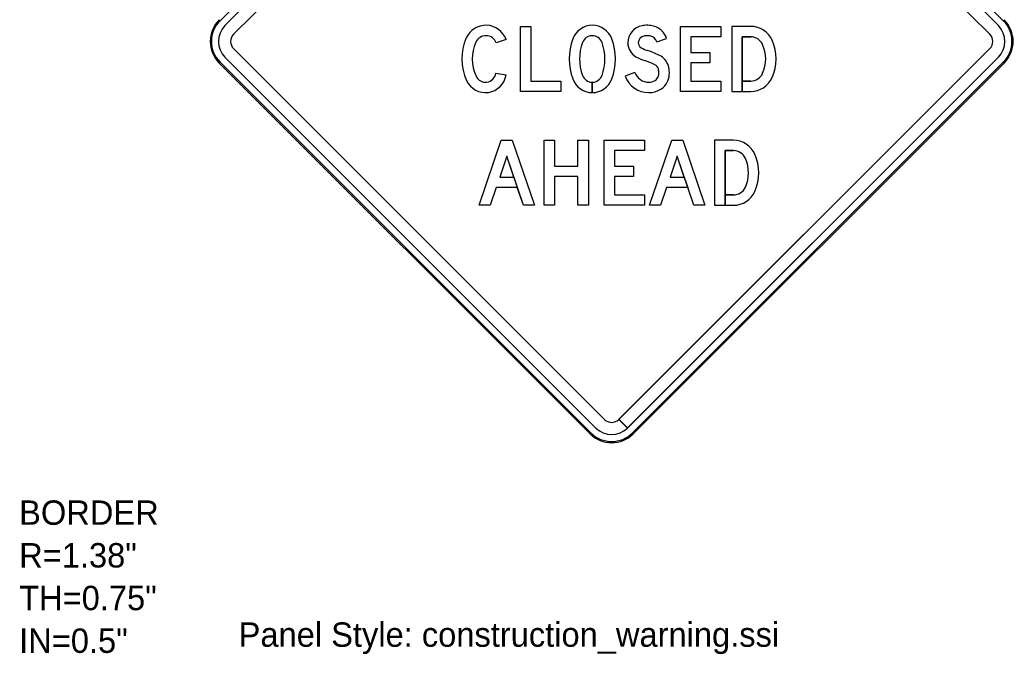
# Model space of a CAD drawing. Extents: x 1788.1 to 1851.2, y 237.2 to 283.4.
# Drawn here: x 1804.67 to 1810.78, y 273.18 to 277.08 of the extents above; entities that cross this region are included whole.
import ezdxf

# ---------------------------------------------------------------- set-up
doc = ezdxf.new("R2010")
doc.units = 0
for name, color, linetype in [('GSBWFILL', 7, 'Continuous'), ('GSCOLORFILL', 7, 'Continuous'), ('GSDIMS', 7, 'Continuous'), ('GSOUTLINE', 7, 'Continuous')]:
    doc.layers.add(name, color=color, linetype=linetype)

msp = doc.modelspace()

# ---------------------------------------------------------------- linework, layer by layer
at = {"layer": 'GSBWFILL'}
for p, q in [((1808.2153, 279.3253), (1805.9352, 277.0452)), ((1810.6898, 277.0452), (1808.4097, 279.3253)), ((1805.9882, 276.9922), (1808.2683, 279.2722)), ((1808.3567, 279.2722), (1810.6368, 276.9922)), ((1808.2683, 274.6237), (1805.9882, 276.9038)), ((1807.6632, 276.9606), (1807.6031, 276.9387)), ((1810.6368, 276.9038), (1808.3572, 274.6242)), ((1805.9352, 276.8507), (1808.2153, 274.5707)), ((1808.4103, 274.5712), (1810.6898, 276.8507)), ((1805.8997, 276.8152), (1808.1797, 274.5351)), ((1808.4453, 274.5351), (1810.7253, 276.8152)), ((1807.5999, 276.7519), (1807.6632, 276.7425)), ((1808.1932, 276.6974), (1808.1932, 276.6334)), ((1808.1933, 276.6334), (1808.1933, 276.6974)), ((1809.1674, 276.7044), (1809.1153, 276.7044)), ((1809.0614, 276.0044), (1809.0093, 276.0044)), ((1808.4097, 274.5707), (1808.3567, 274.6237)), ((1808.3572, 274.6242), (1808.4103, 274.5712))]:
    msp.add_line(p, q, dxfattribs=at)
for points in [[(1807.8152, 276.7044), (1807.9992, 276.7044), (1807.9992, 276.6404), (1807.7512, 276.6404), (1807.7512, 277.0404), (1807.8152, 277.0404)], [(1808.9832, 276.9764), (1808.7992, 276.9764), (1808.7992, 276.8804), (1808.9156, 276.8804), (1808.9156, 276.8164), (1808.7992, 276.8164), (1808.7992, 276.7044), (1808.9832, 276.7044), (1808.9832, 276.6404), (1808.7352, 276.6404), (1808.7352, 277.0404), (1808.9832, 277.0404)], [(1807.4973, 275.9404), (1807.6333, 276.3404), (1807.7013, 276.3404), (1807.8373, 275.9404), (1807.7697, 275.9404), (1807.6673, 276.2416), (1807.624, 276.1143), (1807.7105, 276.1143), (1807.7323, 276.0503), (1807.6023, 276.0503), (1807.5649, 275.9404)], [(1807.8973, 276.3404), (1807.9613, 276.3404), (1807.9613, 276.1804), (1808.1053, 276.1804), (1808.1053, 276.3404), (1808.1693, 276.3404), (1808.1693, 275.9404), (1808.1053, 275.9404), (1808.1053, 276.1164), (1807.9613, 276.1164), (1807.9613, 275.9404), (1807.8973, 275.9404)], [(1808.5133, 276.2764), (1808.3293, 276.2764), (1808.3293, 276.1804), (1808.4456, 276.1804), (1808.4456, 276.1164), (1808.3293, 276.1164), (1808.3293, 276.0044), (1808.5133, 276.0044), (1808.5133, 275.9404), (1808.2653, 275.9404), (1808.2653, 276.3404), (1808.5133, 276.3404)], [(1808.5453, 275.9404), (1808.6813, 276.3404), (1808.7493, 276.3404), (1808.8853, 275.9404), (1808.8177, 275.9404), (1808.7153, 276.2416), (1808.672, 276.1143), (1808.7585, 276.1143), (1808.7803, 276.0503), (1808.6503, 276.0503), (1808.6129, 275.9404)]]:
    msp.add_lwpolyline(points, close=True, dxfattribs=at)
for points in [[(1809.1674, 277.0404), (1809.0512, 277.0404), (1809.0512, 276.6404), (1809.1152, 276.6404), (1809.1152, 276.9764), (1809.1674, 276.9764)], [(1808.5892, 276.9461), (1808.6499, 276.9664)], [(1808.4551, 276.7567), (1808.3952, 276.7341)], [(1809.1153, 276.7044), (1809.1153, 276.6404), (1809.1674, 276.6404)], [(1809.0614, 276.3404), (1808.9453, 276.3404), (1808.9453, 275.9404), (1809.0093, 275.9404), (1809.0093, 276.2764), (1809.0614, 276.2764)], [(1809.0093, 276.0044), (1809.0093, 275.9404), (1809.0614, 275.9404)]]:
    msp.add_lwpolyline(points, dxfattribs=at)
for centre, radius, start, end in [((1806.0324, 276.948), 0.1878, 135, 225), ((1806.0324, 276.948), 0.1375, 135, 225), ((1809.1674, 276.8964), 0.144, 23.94109, 90), ((1810.5926, 276.948), 0.1375, 315, 45), ((1810.5926, 276.948), 0.1878, 315, 45), ((1806.0324, 276.948), 0.0625, 135, 225), ((1809.1674, 276.8964), 0.08, 23.94109, 90), ((1810.5926, 276.948), 0.0625, 315, 45), ((1809.0412, 276.8404), 0.218, 336.05891, 23.94109), ((1809.0412, 276.8404), 0.282, 336.05891, 23.94109), ((1809.1674, 276.7844), 0.08, 270, 336.05891), ((1809.1674, 276.7844), 0.144, 270, 336.05891), ((1809.0614, 276.1964), 0.144, 23.94109, 90), ((1809.0614, 276.1964), 0.08, 23.94109, 90), ((1808.9353, 276.1404), 0.282, 336.05891, 23.94109), ((1808.9353, 276.1404), 0.218, 336.05891, 23.94109), ((1809.0614, 276.0844), 0.08, 270, 336.05891), ((1809.0614, 276.0844), 0.144, 270, 336.05891), ((1808.3125, 274.6679), 0.0625, 225, 315), ((1808.3125, 274.6679), 0.1878, 225, 315), ((1808.3125, 274.6679), 0.1375, 225, 315)]:
    msp.add_arc(centre, radius, start, end, dxfattribs=at)
for centre, major_axis, start_param, end_param in [((1807.5392, 276.9154), (0, 0.132), 5.061866, 7.434148), ((1808.1932, 276.9194), (0, 0.128), 5.063177, 7.503193), ((1808.5184, 276.9395), (0, 0.1066), 0.175685, 1.570796), ((1808.5301, 276.8736), (0, 0.1735), 0.090794, 0.175685), ((1808.5355, 276.8147), (0, 0.2326), 6.283185, 6.373979), ((1808.5355, 276.92), (0, 0.1273), 6.012094, 6.283185), ((1808.538, 276.9291), (0, 0.118), 5.034126, 6.012094), ((1807.7072, 276.8404), (0, 0.316), 1.150963, 2.004476), ((1807.5392, 276.9154), (0, 0.068), 5.061866, 7.434148), ((1808.4091, 276.8404), (0, 0.3579), 1.220008, 1.921585), ((1808.1932, 276.9194), (0, 0.064), 5.063177, 7.503193), ((1807.9773, 276.8404), (0, 0.3579), 4.361601, 5.063177), ((1808.5184, 276.9395), (0, 0.0426), 0.175685, 1.570796), ((1808.5301, 276.8736), (0, 0.1095), 0.090794, 0.175685), ((1808.5355, 276.8147), (0, 0.1686), 0, 0.090794), ((1808.5355, 276.92), (0, 0.0633), 6.012094, 6.283185), ((1808.538, 276.9291), (0, 0.054), 5.034126, 6.012094), ((1807.7072, 276.8404), (0, 0.252), 1.150963, 2.004476), ((1808.4091, 276.8404), (0, 0.2939), 1.220008, 1.921585), ((1807.9773, 276.8404), (0, 0.2939), 4.361601, 5.063177), ((1808.5104, 276.9395), (0, 0.0986), 1.570796, 2.627164), ((1808.5104, 276.9395), (0, 0.0346), 1.570796, 2.627164), ((1808.6008, 277.0994), (0, 0.2182), 2.627164, 2.834816), ((1808.6008, 277.0994), (0, 0.2822), 2.627164, 2.834816), ((1808.3849, 276.418), (0, 0.4965), 5.820582, 5.976409), ((1808.559, 276.7669), (0, 0.1066), 5.010707, 5.820582), ((1808.3849, 276.418), (0, 0.4325), 5.820582, 5.976409), ((1808.559, 276.7669), (0, 0.0426), 5.010707, 5.820582), ((1808.5225, 276.7557), (0, 0.0807), 4.712389, 5.010707), ((1808.5225, 276.7557), (0, 0.1447), 4.712389, 5.010707), ((1807.5366, 276.7614), (0, 0.128), 2.004476, 4.564141), ((1807.5366, 276.7614), (0, 0.064), 2.004476, 4.564141), ((1808.1932, 276.7614), (0, 0.064), 1.921585, 3.141593), ((1808.1932, 276.7614), (0, 0.064), 3.141905, 4.361601), ((1808.5409, 276.789), (0, 0.1556), 1.931277, 3.141593), ((1808.5409, 276.789), (0, 0.0916), 1.931277, 3.141593), ((1808.5554, 276.7476), (0, 0.0462), 3.672524, 4.331279), ((1808.5351, 276.7557), (0, 0.0682), 4.331279, 4.712389), ((1808.5351, 276.7557), (0, 0.1322), 4.331279, 4.712389), ((1808.1932, 276.7614), (0, 0.128), 1.921585, 3.141593), ((1808.1932, 276.7614), (0, 0.128), 3.141749, 4.361601), ((1808.5409, 276.7724), (0, 0.075), 3.141593, 3.672524), ((1808.5554, 276.7476), (0, 0.1102), 3.672524, 4.331279), ((1808.5409, 276.7724), (0, 0.139), 3.141593, 3.672524)]:
    msp.add_ellipse(centre, major_axis=major_axis, ratio=0.999993, start_param=start_param, end_param=end_param, dxfattribs=at)
at = {"layer": 'GSCOLORFILL'}
for p, q in [((1805.905, 277.0754), (1808.185, 279.3555)), ((1808.44, 279.3555), (1810.72, 277.0754)), ((1808.2153, 279.3253), (1805.9352, 277.0452)), ((1810.6898, 277.0452), (1808.4097, 279.3253)), ((1805.9882, 276.9922), (1808.2683, 279.2722)), ((1808.3567, 279.2722), (1810.6368, 276.9922)), ((1808.2683, 274.6237), (1805.9882, 276.9038)), ((1807.6632, 276.9606), (1807.6031, 276.9387)), ((1810.6368, 276.9038), (1808.3572, 274.6242)), ((1805.9352, 276.8507), (1808.2153, 274.5707)), ((1808.4103, 274.5712), (1810.6898, 276.8507)), ((1805.8997, 276.8152), (1808.1797, 274.5351)), ((1805.8997, 276.8152), (1808.1797, 274.5351)), ((1808.185, 274.5404), (1805.905, 276.8205)), ((1810.72, 276.8205), (1808.44, 274.5405)), ((1808.4453, 274.5351), (1810.7253, 276.8152)), ((1808.4453, 274.5352), (1810.7253, 276.8152)), ((1807.5999, 276.7519), (1807.6632, 276.7425)), ((1808.1932, 276.6974), (1808.1932, 276.6334)), ((1808.1933, 276.6334), (1808.1933, 276.6974)), ((1809.1674, 276.7044), (1809.1153, 276.7044)), ((1809.0614, 276.0044), (1809.0093, 276.0044)), ((1808.4097, 274.5707), (1808.3567, 274.6237)), ((1808.3572, 274.6242), (1808.4103, 274.5712)), ((1808.44, 274.5405), (1808.4453, 274.5352)), ((1808.4453, 274.5351), (1808.44, 274.5404))]:
    msp.add_line(p, q, dxfattribs=at)
for points in [[(1807.8152, 276.7044), (1807.9992, 276.7044), (1807.9992, 276.6404), (1807.7512, 276.6404), (1807.7512, 277.0404), (1807.8152, 277.0404)], [(1808.9832, 276.9764), (1808.7992, 276.9764), (1808.7992, 276.8804), (1808.9156, 276.8804), (1808.9156, 276.8164), (1808.7992, 276.8164), (1808.7992, 276.7044), (1808.9832, 276.7044), (1808.9832, 276.6404), (1808.7352, 276.6404), (1808.7352, 277.0404), (1808.9832, 277.0404)], [(1807.4973, 275.9404), (1807.6333, 276.3404), (1807.7013, 276.3404), (1807.8373, 275.9404), (1807.7697, 275.9404), (1807.6673, 276.2416), (1807.624, 276.1143), (1807.7105, 276.1143), (1807.7323, 276.0503), (1807.6023, 276.0503), (1807.5649, 275.9404)], [(1807.8973, 276.3404), (1807.9613, 276.3404), (1807.9613, 276.1804), (1808.1053, 276.1804), (1808.1053, 276.3404), (1808.1693, 276.3404), (1808.1693, 275.9404), (1808.1053, 275.9404), (1808.1053, 276.1164), (1807.9613, 276.1164), (1807.9613, 275.9404), (1807.8973, 275.9404)], [(1808.5133, 276.2764), (1808.3293, 276.2764), (1808.3293, 276.1804), (1808.4456, 276.1804), (1808.4456, 276.1164), (1808.3293, 276.1164), (1808.3293, 276.0044), (1808.5133, 276.0044), (1808.5133, 275.9404), (1808.2653, 275.9404), (1808.2653, 276.3404), (1808.5133, 276.3404)], [(1808.5453, 275.9404), (1808.6813, 276.3404), (1808.7493, 276.3404), (1808.8853, 275.9404), (1808.8177, 275.9404), (1808.7153, 276.2416), (1808.672, 276.1143), (1808.7585, 276.1143), (1808.7803, 276.0503), (1808.6503, 276.0503), (1808.6129, 275.9404)]]:
    msp.add_lwpolyline(points, close=True, dxfattribs=at)
for points in [[(1809.1674, 277.0404), (1809.0512, 277.0404), (1809.0512, 276.6404), (1809.1152, 276.6404), (1809.1152, 276.9764), (1809.1674, 276.9764)], [(1808.5892, 276.9461), (1808.6499, 276.9664)], [(1808.4551, 276.7567), (1808.3952, 276.7341)], [(1809.1153, 276.7044), (1809.1153, 276.6404), (1809.1674, 276.6404)], [(1809.0614, 276.3404), (1808.9453, 276.3404), (1808.9453, 275.9404), (1809.0093, 275.9404), (1809.0093, 276.2764), (1809.0614, 276.2764)], [(1809.0093, 276.0044), (1809.0093, 275.9404), (1809.0614, 275.9404)]]:
    msp.add_lwpolyline(points, dxfattribs=at)
for centre, radius, start, end in [((1806.0324, 276.948), 0.1878, 135, 225), ((1806.0324, 276.948), 0.1878, 135, 225), ((1806.0324, 276.948), 0.1802, 135, 225), ((1806.0324, 276.948), 0.1375, 135, 225), ((1809.1674, 276.8964), 0.144, 23.94109, 90), ((1810.5926, 276.948), 0.1375, 315, 45), ((1810.5926, 276.948), 0.1802, 315, 45), ((1810.5926, 276.948), 0.1878, 315, 45), ((1810.5926, 276.948), 0.1878, 315, 45), ((1806.0324, 276.948), 0.0625, 135, 225), ((1809.1674, 276.8964), 0.08, 23.94109, 90), ((1810.5926, 276.948), 0.0625, 315, 45), ((1809.0412, 276.8404), 0.218, 336.05891, 23.94109), ((1809.0412, 276.8404), 0.282, 336.05891, 23.94109), ((1809.1674, 276.7844), 0.08, 270, 336.05891), ((1809.1674, 276.7844), 0.144, 270, 336.05891), ((1809.0614, 276.1964), 0.144, 23.94109, 90), ((1809.0614, 276.1964), 0.08, 23.94109, 90), ((1808.9353, 276.1404), 0.282, 336.05891, 23.94109), ((1808.9353, 276.1404), 0.218, 336.05891, 23.94109), ((1809.0614, 276.0844), 0.08, 270, 336.05891), ((1809.0614, 276.0844), 0.144, 270, 336.05891), ((1808.3125, 274.6679), 0.0625, 225, 315), ((1808.3125, 274.6679), 0.1878, 225, 315), ((1808.3125, 274.6679), 0.1878, 225, 315), ((1808.3125, 274.6679), 0.1802, 225, 315), ((1808.3125, 274.6679), 0.1375, 225, 315)]:
    msp.add_arc(centre, radius, start, end, dxfattribs=at)
for centre, major_axis, start_param, end_param in [((1807.5392, 276.9154), (0, 0.132), 5.061866, 7.434148), ((1808.1932, 276.9194), (0, 0.128), 5.063177, 7.503193), ((1808.5184, 276.9395), (0, 0.1066), 0.175685, 1.570796), ((1808.5301, 276.8736), (0, 0.1735), 0.090794, 0.175685), ((1808.5355, 276.8147), (0, 0.2326), 6.283185, 6.373979), ((1808.5355, 276.92), (0, 0.1273), 6.012094, 6.283185), ((1808.538, 276.9291), (0, 0.118), 5.034126, 6.012094), ((1807.7072, 276.8404), (0, 0.316), 1.150963, 2.004476), ((1807.5392, 276.9154), (0, 0.068), 5.061866, 7.434148), ((1808.4091, 276.8404), (0, 0.3579), 1.220008, 1.921585), ((1808.1932, 276.9194), (0, 0.064), 5.063177, 7.503193), ((1807.9773, 276.8404), (0, 0.3579), 4.361601, 5.063177), ((1808.5184, 276.9395), (0, 0.0426), 0.175685, 1.570796), ((1808.5301, 276.8736), (0, 0.1095), 0.090794, 0.175685), ((1808.5355, 276.8147), (0, 0.1686), 0, 0.090794), ((1808.5355, 276.92), (0, 0.0633), 6.012094, 6.283185), ((1808.538, 276.9291), (0, 0.054), 5.034126, 6.012094), ((1807.7072, 276.8404), (0, 0.252), 1.150963, 2.004476), ((1808.4091, 276.8404), (0, 0.2939), 1.220008, 1.921585), ((1807.9773, 276.8404), (0, 0.2939), 4.361601, 5.063177), ((1808.5104, 276.9395), (0, 0.0986), 1.570796, 2.627164), ((1808.5104, 276.9395), (0, 0.0346), 1.570796, 2.627164), ((1808.6008, 277.0994), (0, 0.2182), 2.627164, 2.834816), ((1808.6008, 277.0994), (0, 0.2822), 2.627164, 2.834816), ((1808.3849, 276.418), (0, 0.4965), 5.820582, 5.976409), ((1808.559, 276.7669), (0, 0.1066), 5.010707, 5.820582), ((1808.3849, 276.418), (0, 0.4325), 5.820582, 5.976409), ((1808.559, 276.7669), (0, 0.0426), 5.010707, 5.820582), ((1808.5225, 276.7557), (0, 0.0807), 4.712389, 5.010707), ((1808.5225, 276.7557), (0, 0.1447), 4.712389, 5.010707), ((1807.5366, 276.7614), (0, 0.128), 2.004476, 4.564141), ((1807.5366, 276.7614), (0, 0.064), 2.004476, 4.564141), ((1808.1932, 276.7614), (0, 0.064), 1.921585, 3.141593), ((1808.1932, 276.7614), (0, 0.064), 3.141905, 4.361601), ((1808.5409, 276.789), (0, 0.1556), 1.931277, 3.141593), ((1808.5409, 276.789), (0, 0.0916), 1.931277, 3.141593), ((1808.5554, 276.7476), (0, 0.0462), 3.672524, 4.331279), ((1808.5351, 276.7557), (0, 0.0682), 4.331279, 4.712389), ((1808.5351, 276.7557), (0, 0.1322), 4.331279, 4.712389), ((1808.1932, 276.7614), (0, 0.128), 1.921585, 3.141593), ((1808.1932, 276.7614), (0, 0.128), 3.141749, 4.361601), ((1808.5409, 276.7724), (0, 0.075), 3.141593, 3.672524), ((1808.5554, 276.7476), (0, 0.1102), 3.672524, 4.331279), ((1808.5409, 276.7724), (0, 0.139), 3.141593, 3.672524)]:
    msp.add_ellipse(centre, major_axis=major_axis, ratio=0.999993, start_param=start_param, end_param=end_param, dxfattribs=at)
at = {"layer": 'GSOUTLINE'}
for p, q in [((1808.2153, 279.3253), (1805.9352, 277.0452)), ((1810.6898, 277.0452), (1808.4097, 279.3253)), ((1808.2683, 279.2722), (1805.9882, 276.9922)), ((1810.6368, 276.9922), (1808.3567, 279.2722)), ((1809.1674, 277.0404), (1809.0512, 277.0404)), ((1809.1674, 276.9764), (1809.1152, 276.9764)), ((1805.9882, 276.9038), (1808.2683, 274.6237)), ((1807.6632, 276.9606), (1807.6031, 276.9387)), ((1808.3567, 274.6237), (1810.6368, 276.9038)), ((1805.9352, 276.8507), (1808.2153, 274.5707)), ((1808.4097, 274.5707), (1810.6898, 276.8507)), ((1805.8997, 276.8152), (1808.1797, 274.5351)), ((1808.4453, 274.5351), (1810.7253, 276.8152)), ((1807.5999, 276.7519), (1807.6632, 276.7425)), ((1809.0614, 276.3404), (1808.9453, 276.3404)), ((1809.0614, 276.2764), (1809.0093, 276.2764))]:
    msp.add_line(p, q, dxfattribs=at)
for points in [[(1807.8152, 276.7044), (1807.9992, 276.7044), (1807.9992, 276.6404), (1807.7512, 276.6404), (1807.7512, 277.0404), (1807.8152, 277.0404)], [(1808.9832, 276.9764), (1808.7992, 276.9764), (1808.7992, 276.8804), (1808.9156, 276.8804), (1808.9156, 276.8164), (1808.7992, 276.8164), (1808.7992, 276.7044), (1808.9832, 276.7044), (1808.9832, 276.6404), (1808.7352, 276.6404), (1808.7352, 277.0404), (1808.9832, 277.0404)], [(1807.6023, 276.0503), (1807.5649, 275.9404), (1807.4973, 275.9404), (1807.6333, 276.3404), (1807.7013, 276.3404), (1807.8373, 275.9404), (1807.7697, 275.9404), (1807.7323, 276.0503)], [(1807.8973, 276.3404), (1807.9613, 276.3404), (1807.9613, 276.1804), (1808.1053, 276.1804), (1808.1053, 276.3404), (1808.1693, 276.3404), (1808.1693, 275.9404), (1808.1053, 275.9404), (1808.1053, 276.1164), (1807.9613, 276.1164), (1807.9613, 275.9404), (1807.8973, 275.9404)], [(1808.5133, 276.2764), (1808.3293, 276.2764), (1808.3293, 276.1804), (1808.4456, 276.1804), (1808.4456, 276.1164), (1808.3293, 276.1164), (1808.3293, 276.0044), (1808.5133, 276.0044), (1808.5133, 275.9404), (1808.2653, 275.9404), (1808.2653, 276.3404), (1808.5133, 276.3404)], [(1808.6503, 276.0503), (1808.6129, 275.9404), (1808.5453, 275.9404), (1808.6813, 276.3404), (1808.7493, 276.3404), (1808.8853, 275.9404), (1808.8177, 275.9404), (1808.7803, 276.0503)], [(1807.624, 276.1143), (1807.7106, 276.1143), (1807.6673, 276.2416)], [(1808.672, 276.1143), (1808.7586, 276.1143), (1808.7153, 276.2416)]]:
    msp.add_lwpolyline(points, close=True, dxfattribs=at)
for points in [[(1809.0512, 277.0404), (1809.0512, 276.6404), (1809.1674, 276.6404)], [(1808.5892, 276.9461), (1808.6499, 276.9664)], [(1809.1152, 276.9764), (1809.1152, 276.7044), (1809.1674, 276.7044)], [(1808.4551, 276.7567), (1808.3952, 276.7341)], [(1808.9453, 276.3404), (1808.9453, 275.9404), (1809.0614, 275.9404)], [(1809.0093, 276.2764), (1809.0093, 276.0044), (1809.0614, 276.0044)]]:
    msp.add_lwpolyline(points, dxfattribs=at)
for centre, radius, start, end in [((1806.0324, 276.948), 0.1878, 135, 225), ((1806.0324, 276.948), 0.1375, 135, 225), ((1809.1674, 276.8964), 0.144, 23.94109, 90), ((1810.5926, 276.948), 0.1375, 315, 45), ((1810.5926, 276.948), 0.1878, 315, 45), ((1806.0324, 276.948), 0.0625, 135, 225), ((1809.1674, 276.8964), 0.08, 23.94109, 90), ((1810.5926, 276.948), 0.0625, 315, 45), ((1809.0412, 276.8404), 0.218, 336.05891, 23.94109), ((1809.0412, 276.8404), 0.282, 336.05891, 23.94109), ((1809.1674, 276.7844), 0.08, 270, 336.05891), ((1809.1674, 276.7844), 0.144, 270, 336.05891), ((1809.0614, 276.1964), 0.144, 23.94109, 90), ((1809.0614, 276.1964), 0.08, 23.94109, 90), ((1808.9353, 276.1404), 0.282, 336.05891, 23.94109), ((1808.9353, 276.1404), 0.218, 336.05891, 23.94109), ((1809.0614, 276.0844), 0.08, 270, 336.05891), ((1809.0614, 276.0844), 0.144, 270, 336.05891), ((1808.3125, 274.6679), 0.0625, 225, 315), ((1808.3125, 274.6679), 0.1878, 225, 315), ((1808.3125, 274.6679), 0.1375, 225, 315)]:
    msp.add_arc(centre, radius, start, end, dxfattribs=at)
for centre, major_axis, start_param, end_param in [((1807.5392, 276.9154), (0, 0.132), 5.061866, 7.434148), ((1808.1932, 276.9194), (0, 0.128), 5.063177, 7.503193), ((1808.5184, 276.9395), (0, 0.1066), 0.175685, 1.570796), ((1808.5301, 276.8736), (0, 0.1735), 0.090794, 0.175685), ((1808.5355, 276.8147), (0, 0.2326), 6.283185, 6.373979), ((1808.5355, 276.92), (0, 0.1273), 6.012094, 6.283185), ((1808.538, 276.9291), (0, 0.118), 5.034126, 6.012094), ((1807.7072, 276.8404), (0, 0.316), 1.150963, 2.004476), ((1807.5392, 276.9154), (0, 0.068), 5.061866, 7.434148), ((1808.4091, 276.8404), (0, 0.3579), 1.220008, 1.921585), ((1808.1932, 276.9194), (0, 0.064), 5.063177, 7.503193), ((1807.9773, 276.8404), (0, 0.3579), 4.361601, 5.063177), ((1808.5184, 276.9395), (0, 0.0426), 0.175685, 1.570796), ((1808.5301, 276.8736), (0, 0.1095), 0.090794, 0.175685), ((1808.5355, 276.8147), (0, 0.1686), 0, 0.090794), ((1808.5355, 276.92), (0, 0.0633), 6.012094, 6.283185), ((1808.538, 276.9291), (0, 0.054), 5.034126, 6.012094), ((1807.7072, 276.8404), (0, 0.252), 1.150963, 2.004476), ((1808.4091, 276.8404), (0, 0.2939), 1.220008, 1.921585), ((1807.9773, 276.8404), (0, 0.2939), 4.361601, 5.063177), ((1808.5104, 276.9395), (0, 0.0986), 1.570796, 2.627164), ((1808.5104, 276.9395), (0, 0.0346), 1.570796, 2.627164), ((1808.6008, 277.0994), (0, 0.2182), 2.627164, 2.834816), ((1808.6008, 277.0994), (0, 0.2822), 2.627164, 2.834816), ((1808.3849, 276.418), (0, 0.4965), 5.820582, 5.976409), ((1808.559, 276.7669), (0, 0.1066), 5.010707, 5.820582), ((1808.3849, 276.418), (0, 0.4325), 5.820582, 5.976409), ((1808.559, 276.7669), (0, 0.0426), 5.010707, 5.820582), ((1808.5225, 276.7557), (0, 0.0807), 4.712389, 5.010707), ((1808.5225, 276.7557), (0, 0.1447), 4.712389, 5.010707), ((1807.5366, 276.7614), (0, 0.128), 2.004476, 4.564141), ((1807.5366, 276.7614), (0, 0.064), 2.004476, 4.564141), ((1808.1932, 276.7614), (0, 0.064), 1.921585, 4.361601), ((1808.5409, 276.789), (0, 0.1556), 1.931277, 3.141593), ((1808.5409, 276.789), (0, 0.0916), 1.931277, 3.141593), ((1808.5554, 276.7476), (0, 0.0462), 3.672524, 4.331279), ((1808.5351, 276.7557), (0, 0.0682), 4.331279, 4.712389), ((1808.5351, 276.7557), (0, 0.1322), 4.331279, 4.712389), ((1808.1932, 276.7614), (0, 0.128), 1.921585, 4.361601), ((1808.5409, 276.7724), (0, 0.075), 3.141593, 3.672524), ((1808.5554, 276.7476), (0, 0.1102), 3.672524, 4.331279), ((1808.5409, 276.7724), (0, 0.139), 3.141593, 3.672524)]:
    msp.add_ellipse(centre, major_axis=major_axis, ratio=0.999993, start_param=start_param, end_param=end_param, dxfattribs=at)

# ---------------------------------------------------------------- texts
at = {"layer": 'GSDIMS'}
for s, p in [('BORDER', (1804.6699, 273.9753)), ('R=1.38"', (1804.6699, 273.7128)), ('TH=0.75"', (1804.6699, 273.4503)), ('Panel Style: construction_warning.ssi', (1806.0194, 273.2253)), ('IN=0.5"', (1804.6699, 273.1878))]:
    msp.add_text(s, height=0.15, dxfattribs=at).set_placement(p)

doc.saveas('drawing.dxf')
